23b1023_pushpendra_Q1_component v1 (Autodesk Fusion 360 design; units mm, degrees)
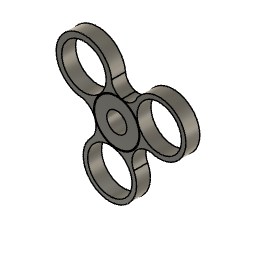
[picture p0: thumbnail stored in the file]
sketch "Sketch1" plane through (0, 0, 0) normal (0, 1, 0) x axis (1, 0, 0)
  circle C1 centre (0, 0) radius 15
  circle C2 centre (0, 0) radius 18
  circle C3 centre (0, 0) radius 40
  circle C4 centre (0, 0) radius 41.5
  circle C5 centre (-59.0551, -57.0604) radius 40
  circle C6 centre (76.5617, -29.6063) radius 40
  circle C7 centre (-12.3884, 81.5485) radius 40
  arc A1 centre (58.2437, 46.5927) radius 30.8086 clockwise from (62.9862, 16.1512) to (30.6315, 60.2579)
  arc A2 centre (14.0284, -63.3201) radius 23.3554 clockwise from (-9.2704, -61.6955) to (36.5557, -57.1559)
  arc A3 centre (-70.406, 24.8346) radius 33.1576 clockwise from (-46.0144, 47.2952) to (-61.5685, -7.1236)
  arc A4 centre (-12.3884, 81.5485) radius 48 clockwise from (-20.6405, 34.2632) to (-22.7823, 34.6874)
  arc A5 centre (-12.3884, 81.5485) radius 48 clockwise from (11.4532, 39.8883) to (9.534, 38.8472)
  arc A6 centre (-12.3884, 81.5485) radius 48 clockwise from (-46.0144, 47.2952) to (30.6315, 60.2579)
  arc A7 centre (76.5617, -29.6063) radius 48 clockwise from (39.9732, 1.4628) to (41.3874, 3.0552)
  arc A8 centre (-59.0551, -57.0604) radius 50 clockwise from (-12.8854, -37.8678) to (-12.1754, -39.6738)
  arc A9 centre (-59.0551, -57.0604) radius 50 clockwise from (-40.0686, -10.8055) to (-38.288, -11.5771)
  arc A10 centre (-59.0551, -57.0604) radius 50 clockwise from (-9.2704, -61.6955) to (-61.5685, -7.1236)
  arc A11 centre (76.5617, -29.6063) radius 48 clockwise from (28.5643, -30.1054) to (28.5894, -27.9758)
  arc A12 centre (76.5617, -29.6063) radius 48 clockwise from (61.4431, 15.9506) to (32.9151, -49.5807)
  point P1 (0, 0)
  point P2 (0, 0)
  point P4 (0, 0)
  point P12 (30.6315, 60.2579)
  point P15 (-9.2704, -61.6955)
  point P18 (-61.5685, -7.1236)
  point P21 (-20.6405, 34.2632)
  point P22 (9.534, 38.8472)
  point P23 (-22.7823, 34.6874)
  point P25 (11.4532, 39.8883)
  point P27 (61.4431, 15.9506)
  point P28 (41.3874, 3.0552)
  point P29 (39.9732, 1.4628)
  point P30 (28.5894, -27.9758)
  point P32 (-12.8854, -37.8678)
  point P33 (-38.288, -11.5771)
  point P34 (-9.2704, -61.6955)
  point P35 (-12.1754, -39.6738)
  point P37 (-40.0686, -10.8055)
  point P39 (28.5643, -30.1054)
  point P40 (32.9151, -49.5807)
  coincident P1 P2
  concentric C1 C2
  coincident P1 P4
  concentric C1 C4
  concentric C5 A9
  concentric C7 A5
  concentric C6 A7
  tangent A1 A5
  coincident P12 A5
  tangent C4 A2
  coincident P15 A9
  tangent C4 A3
  coincident P18 A9
  coincident C3 P21
  coincident C3 P22
  coincident C4 P23
  concentric A4 A5
  coincident C4 P25
  concentric A5 A6
  coincident A1 P27
  coincident C4 P28
  coincident C3 P29
  coincident C3 P30
  concentric A7 A11
  coincident C3 P32
  coincident C3 P33
  coincident A2 P34
  coincident C4 P35
  concentric A8 A9
  coincident C4 P37
  concentric A9 A10
  coincident C4 P39
  coincident A2 P40
  concentric A11 A12
  dimension "d1" diameter C1 = 30
  dimension "d2" diameter C2 = 36
  dimension "d3" diameter C3 = 80
  dimension "d4" diameter C4 = 83
  dimension "d7" diameter C5 = 80
  dimension "d8" diameter C6 = 80
  dimension "d9" diameter C7 = 80
  dimension "d10" diameter A9 = 100
  dimension "d11" diameter A5 = 96
  dimension "d12" diameter A7 = 96
  dimension "d13" radius A1 = 30.8086
extrude "Extrude1" new body sketch "Sketch1" profile of C2 C3 C4 C5 C6 C7 A10 A6 A12 A1 A2 A3 along normal blind 25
